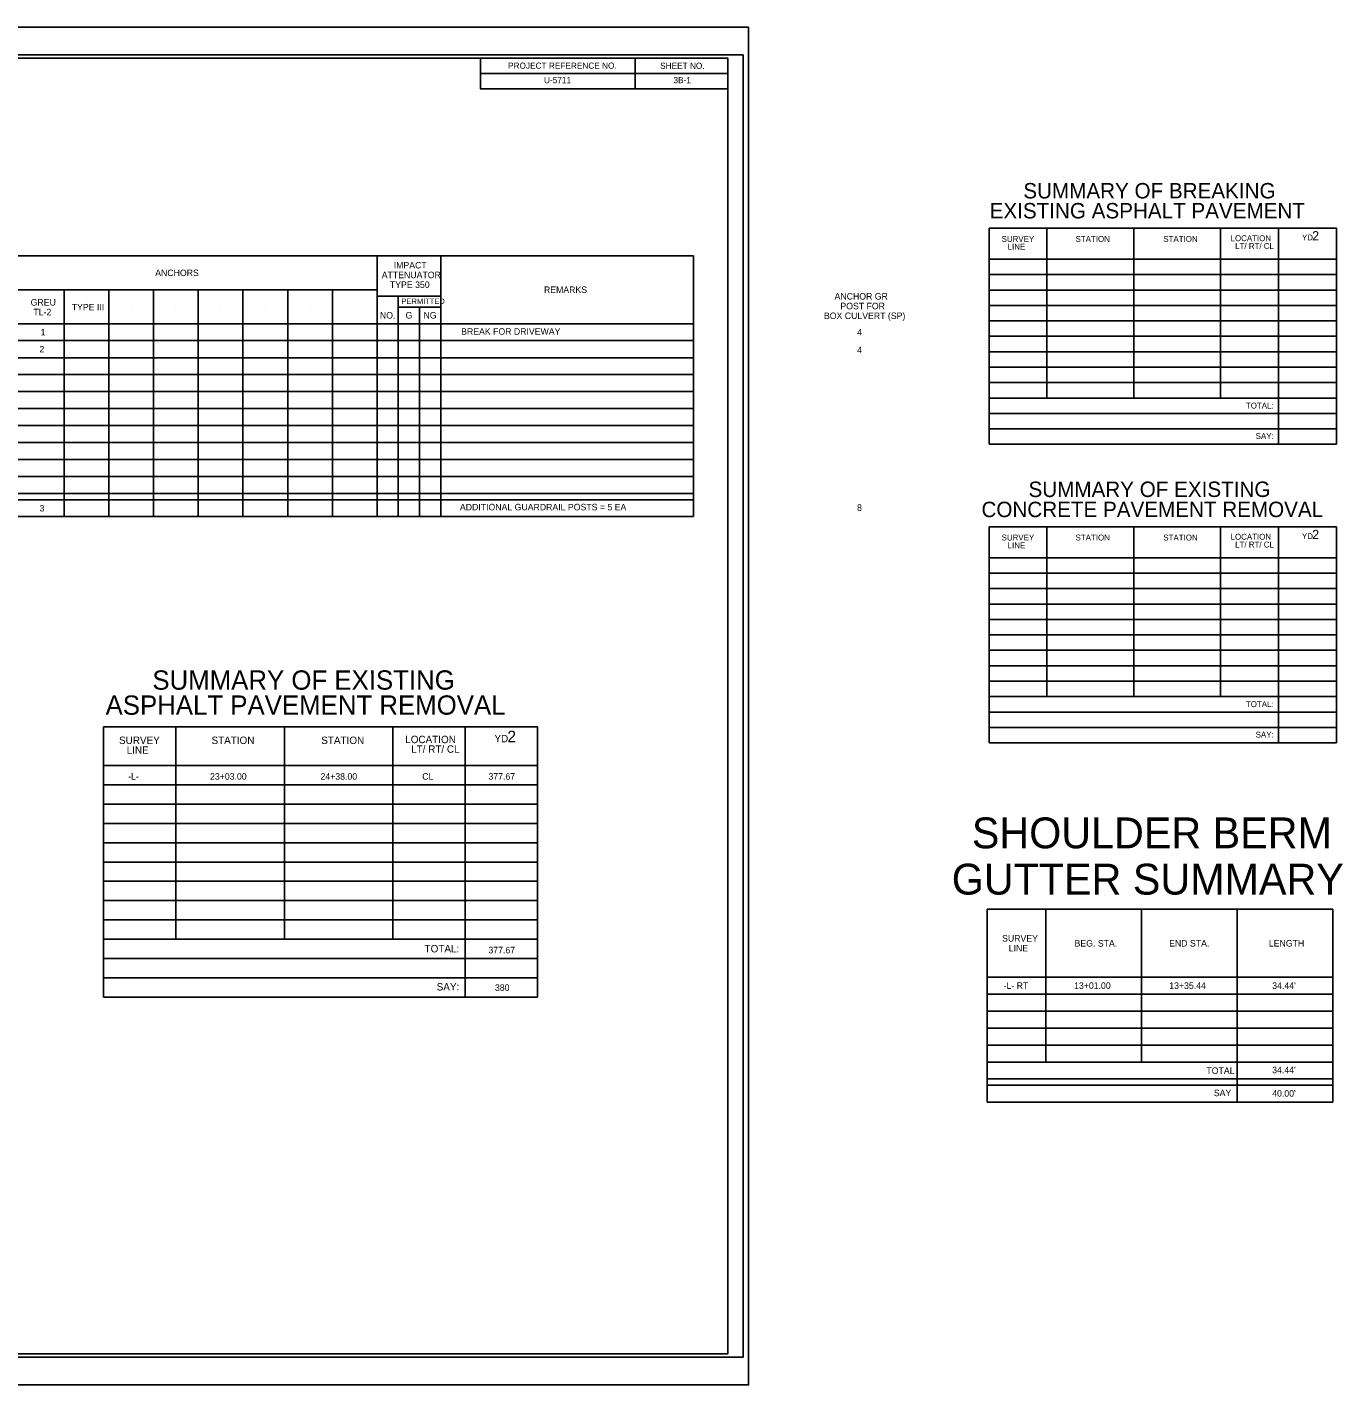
# Model space of a CAD drawing. Extents: x 1852861 to 1855026, y 258638 to 259738.
# Drawn here: x 1853961 to 1855026, y 258638 to 259738 of the extents above; entities that cross this region are included whole.
import ezdxf

# ---------------------------------------------------------------- set-up
doc = ezdxf.new("R2010")
doc.units = 0
for name, color, linetype in [('Old_Level_44', 7, 'Continuous'), ('Sheet Cutting Line CELL', 7, 'Continuous'), ('Sheet Plot Border Inside CELL', 7, 'Continuous'), ('Sheet Plot Border Outside CELL', 7, 'Continuous'), ('Sheet Summary Combination CELL', 7, 'Continuous'), ('Sheet Summary Combination Grid CELL', 7, 'Continuous'), ('Sheet Summary Guardrail CELL', 7, 'Continuous')]:
    doc.layers.add(name, color=color, linetype=linetype)

msp = doc.modelspace()

# ---------------------------------------------------------------- linework, layer by layer
at = {"layer": 'Sheet Cutting Line CELL'}
for p, q in [((1854545.1, 259738.5), (1852861.1, 259738.5)), ((1852861.1, 258638.5), (1854545.1, 258638.5))]:
    msp.add_line(p, q, dxfattribs=at)
at = {"layer": 'Sheet Plot Border Inside CELL'}
msp.add_lwpolyline([(1854540.6, 259716), (1852874.1, 259716), (1852874.1, 258660.9), (1854540.6, 258660.9)], close=True, dxfattribs=at)
at = {"layer": 'Sheet Plot Border Outside CELL'}
msp.add_lwpolyline([(1854545.1, 259738.5), (1852861.1, 259738.5), (1852861.1, 258638.5), (1854545.1, 258638.5)], close=True, dxfattribs=at)
at = {"layer": 'Sheet Summary Combination CELL'}
for p, q in [((1854453.1, 259713.4), (1854453.1, 259688.4)), ((1854328, 259700.9), (1854528.1, 259700.9)), ((1854328, 259688.4), (1854528.1, 259688.4)), ((1854881.1, 259575.5), (1854881.1, 259575.5)), ((1854887.3, 259575.4), (1854887.3, 259575.4)), ((1854896.4, 259575.6), (1854896.4, 259575.6)), ((1854902, 259575.5), (1854902, 259575.5)), ((1854881.1, 259333.6), (1854881.1, 259333.6)), ((1854887.3, 259333.5), (1854887.3, 259333.5)), ((1854896.4, 259333.7), (1854896.4, 259333.7)), ((1854902, 259333.6), (1854902, 259333.6)), ((1854199, 259171.4), (1854199, 259171.4)), ((1854206.8, 259171.3), (1854206.8, 259171.3)), ((1854218.1, 259171.5), (1854218.1, 259171.5)), ((1854225.1, 259171.4), (1854225.1, 259171.4))]:
    msp.add_line(p, q, dxfattribs=at)
for points in [[(1854528.1, 259713.5), (1853028.1, 259713.5), (1853028.1, 258663.5), (1854528.1, 258663.5)], [(1854328, 259713.5), (1854528.1, 259713.5), (1854528.1, 259688.4), (1854328, 259688.4)]]:
    msp.add_lwpolyline(points, close=True, dxfattribs=at)
at = {"layer": 'Sheet Summary Combination Grid CELL'}
for p, q in [((1854739.8, 259575.5), (1855021.2, 259575.5)), ((1854739.8, 259575.5), (1854739.8, 259400.5)), ((1854786.7, 259575.5), (1854786.7, 259438)), ((1854857.1, 259575.5), (1854857.1, 259438)), ((1854927.4, 259575.5), (1854927.4, 259438)), ((1854974.3, 259575.5), (1854974.3, 259400.5)), ((1855021.2, 259575.5), (1855021.2, 259400.5)), ((1854739.8, 259550.5), (1855021.2, 259550.5)), ((1854739.8, 259538), (1855021.2, 259538)), ((1854739.8, 259525.5), (1855021.2, 259525.5)), ((1854739.8, 259513), (1855021.2, 259513)), ((1854739.8, 259500.5), (1855021.2, 259500.5)), ((1854739.8, 259488), (1855021.2, 259488)), ((1854739.8, 259475.5), (1855021.2, 259475.5)), ((1854739.8, 259463), (1855021.2, 259463)), ((1854739.8, 259450.5), (1855021.2, 259450.5)), ((1854739.8, 259438), (1855021.2, 259438)), ((1854739.8, 259425.5), (1855021.2, 259425.5)), ((1854739.8, 259413), (1855021.2, 259413)), ((1854739.8, 259400.5), (1855021.2, 259400.5)), ((1854739.8, 259333.6), (1855021.2, 259333.6)), ((1854739.8, 259333.6), (1854739.8, 259158.6)), ((1854786.7, 259333.6), (1854786.7, 259196.1)), ((1854857.1, 259333.6), (1854857.1, 259196.1)), ((1854927.4, 259333.6), (1854927.4, 259196.1)), ((1854974.3, 259333.6), (1854974.3, 259158.6)), ((1855021.2, 259333.6), (1855021.2, 259158.6)), ((1854739.8, 259308.6), (1855021.2, 259308.6)), ((1854739.8, 259296.1), (1855021.2, 259296.1)), ((1854739.8, 259283.6), (1855021.2, 259283.6)), ((1854739.8, 259271.1), (1855021.2, 259271.1)), ((1854739.8, 259258.6), (1855021.2, 259258.6)), ((1854739.8, 259246.1), (1855021.2, 259246.1)), ((1854739.8, 259233.6), (1855021.2, 259233.6)), ((1854739.8, 259221.1), (1855021.2, 259221.1)), ((1854739.8, 259208.6), (1855021.2, 259208.6)), ((1854739.8, 259196.1), (1855021.2, 259196.1)), ((1854739.8, 259183.6), (1855021.2, 259183.6)), ((1854022.4, 259171.5), (1854374.1, 259171.5)), ((1854022.4, 259171.5), (1854022.4, 258952.7)), ((1854081.1, 259171.5), (1854081.1, 258999.6)), ((1854169, 259171.5), (1854169, 258999.6)), ((1854256.9, 259171.5), (1854256.9, 258999.6)), ((1854315.5, 259171.5), (1854315.5, 258952.7)), ((1854374.1, 259171.5), (1854374.1, 258952.7)), ((1854739.8, 259171.1), (1855021.2, 259171.1)), ((1854739.8, 259158.6), (1855021.2, 259158.6)), ((1854022.4, 259140.2), (1854374.1, 259140.2)), ((1854022.4, 259124.6), (1854374.1, 259124.6)), ((1854022.4, 259109), (1854374.1, 259109)), ((1854022.4, 259093.3), (1854374.1, 259093.3)), ((1854022.4, 259077.7), (1854374.1, 259077.7)), ((1854022.4, 259062.1), (1854374.1, 259062.1)), ((1854022.4, 259046.5), (1854374.1, 259046.5)), ((1854022.4, 259030.8), (1854374.1, 259030.8)), ((1854022.4, 259015.2), (1854374.1, 259015.2)), ((1854022.4, 258999.6), (1854374.1, 258999.6)), ((1854022.4, 258984), (1854374.1, 258984)), ((1854022.4, 258968.3), (1854374.1, 258968.3)), ((1854022.4, 258952.7), (1854374.1, 258952.7))]:
    msp.add_line(p, q, dxfattribs=at)
at = {"layer": 'Sheet Summary Guardrail CELL'}
for p, q in [((1853051.9, 259553.2), (1854500.3, 259553.2)), ((1854244.1, 259553.2), (1854244.1, 259341.9)), ((1854295.8, 259553.2), (1854295.8, 259341.9)), ((1854500.3, 259553.2), (1854500.3, 259341.9)), ((1854244.1, 259525.7), (1853736.1, 259525.7)), ((1853990.7, 259525.7), (1853990.7, 259341.9)), ((1854026.9, 259525.7), (1854026.9, 259341.9)), ((1854063.1, 259525.7), (1854063.1, 259341.9)), ((1854099.3, 259525.7), (1854099.3, 259341.9)), ((1854135.5, 259525.7), (1854135.5, 259341.9)), ((1854171.7, 259525.7), (1854171.7, 259341.9)), ((1854207.9, 259525.7), (1854207.9, 259341.9)), ((1854286, 259526), (1854286, 259526)), ((1854008.8, 259518.3), (1854008.8, 259518.3)), ((1854244.1, 259520.5), (1854295.8, 259520.5)), ((1854261.3, 259520.5), (1854261.3, 259341.9)), ((1853972.6, 259512), (1853972.6, 259512)), ((1854045, 259512), (1854045, 259512)), ((1854081.2, 259512), (1854081.2, 259512)), ((1854117.4, 259512), (1854117.4, 259512)), ((1854153.6, 259512), (1854153.6, 259512)), ((1854189.8, 259512), (1854189.8, 259512)), ((1854226, 259512), (1854226, 259512)), ((1854261.3, 259511.7), (1854295.8, 259511.7)), ((1854278.5, 259511.7), (1854278.5, 259341.9)), ((1853051.9, 259498.2), (1854500.3, 259498.2)), ((1853051.9, 259484.5), (1854500.3, 259484.5)), ((1853051.9, 259470.7), (1854500.3, 259470.7)), ((1853051.9, 259457), (1854500.3, 259457)), ((1853051.9, 259443.2), (1854500.3, 259443.2)), ((1853051.9, 259429.5), (1854500.3, 259429.5)), ((1853051.9, 259415.7), (1854500.3, 259415.7)), ((1853051.9, 259402), (1854500.3, 259402)), ((1853051.9, 259388.2), (1854500.3, 259388.2)), ((1853051.9, 259374.5), (1854500.3, 259374.5)), ((1853051.9, 259360.7), (1854500.3, 259360.7)), ((1853051.9, 259355.6), (1854500.3, 259355.6)), ((1853051.9, 259341.9), (1854500.3, 259341.9)), ((1854738.4, 259023.8), (1855018.4, 259023.8)), ((1854738.4, 259023.8), (1854738.4, 258867.4)), ((1854785.7, 259023.8), (1854785.7, 258900)), ((1854863.3, 259023.8), (1854863.3, 258900)), ((1854940.8, 259023.8), (1854940.8, 258867.4)), ((1855018.4, 259023.8), (1855018.4, 258867.4)), ((1854738.4, 258968.8), (1855018.4, 258968.8)), ((1854738.4, 258955), (1855018.4, 258955)), ((1854738.4, 258941.3), (1855018.4, 258941.3)), ((1854738.4, 258927.5), (1855018.4, 258927.5)), ((1854738.4, 258913.8), (1855018.4, 258913.8)), ((1854738.4, 258900), (1855018.4, 258900)), ((1854738.4, 258886.3), (1855018.4, 258886.3)), ((1854738.4, 258881.2), (1855018.4, 258881.2)), ((1854738.4, 258867.4), (1855018.4, 258867.4))]:
    msp.add_line(p, q, dxfattribs=at)

# ---------------------------------------------------------------- texts
at = {"layer": 'Old_Level_44'}
for s, p in [('U-5711', (1854379.3, 259693.1)), ('3B-1', (1854484.2, 259693.1))]:
    msp.add_text(s, height=5, dxfattribs=at).set_placement(p)
at = {"layer": 'Sheet Summary Combination CELL'}
for s, height, p in [('PROJECT REFERENCE NO.', 5, (1854350.2, 259704.8)), ('SHEET NO.', 5, (1854473.4, 259704.7)), ('SURVEY', 4.8, (1854750, 259564.5)), ('STATION', 4.8, (1854809.9, 259564.5)), ('STATION', 4.8, (1854881, 259564.5)), ('LOCATION', 4.8, (1854935.5, 259565.1)), ('LINE', 4.8, (1854754.9, 259558.2)), ('LT/ RT/ CL', 4.8, (1854939.2, 259558.8)), ('TOTAL:', 4.8, (1854947.9, 259429.5)), ('SAY:', 4.8, (1854955.8, 259404.8)), ('SURVEY', 4.8, (1854750, 259322.6)), ('STATION', 4.8, (1854809.9, 259322.6)), ('STATION', 4.8, (1854881, 259322.6)), ('LOCATION', 4.8, (1854935.5, 259323.2)), ('LINE', 4.8, (1854754.9, 259316.3)), ('LT/ RT/ CL', 4.8, (1854939.2, 259316.9)), ('TOTAL:', 4.8, (1854947.9, 259187.6)), ('SURVEY', 6, (1854035.1, 259157.7)), ('STATION', 6, (1854110, 259157.7)), ('STATION', 6, (1854198.9, 259157.7)), ('LOCATION', 6, (1854266.9, 259158.4)), ('SAY:', 4.8, (1854955.8, 259162.9)), ('LINE', 6, (1854041.3, 259149.8)), ('LT/ RT/ CL', 6, (1854271.7, 259150.6)), ('TOTAL:', 6, (1854282.6, 258988.9)), ('SAY:', 6, (1854292.4, 258958))]:
    msp.add_text(s, height=height, dxfattribs=at).set_placement(p)
for s, height, p in [('SUMMARY OF BREAKING', 12.5, (1854767.6, 259599.7)), ('EXISTING ASPHALT PAVEMENT', 12.5, (1854740.3, 259583.5)), ('SUMMARY OF EXISTING', 12.5, (1854771.8, 259357.8)), ('CONCRETE PAVEMENT REMOVAL', 12.5, (1854733.7, 259341.5)), ('SUMMARY OF EXISTING', 15.625, (1854062.1, 259201.7)), ('ASPHALT PAVEMENT REMOVAL', 15.625, (1854024.2, 259181.4))]:
    msp.add_text(s, height=height, rotation=0.0119, dxfattribs=at).set_placement(p)
at = {"layer": 'Sheet Summary Combination Grid CELL'}
for s, height, p in [('YD', 4.8, (1854993.3, 259565.7)), ('2', 7.5, (1855001.6, 259565.7)), ('YD', 4.8, (1854993.3, 259323.7)), ('2', 7.5, (1855001.6, 259323.7)), ('YD', 6, (1854339.2, 259159.1)), ('2', 9.38, (1854349.7, 259159.1))]:
    msp.add_text(s, height=height, dxfattribs=at).set_placement(p)
at = {"layer": 'Sheet Summary Guardrail CELL'}
for s, height, p in [('IMPACT', 5.28, (1854257.6, 259543)), ('ANCHORS', 5.28, (1854064.4, 259536.8)), ('ATTENUATOR', 5.28, (1854247.9, 259535.1)), ('TYPE 350', 5.28, (1854254.5, 259527.2)), ('REMARKS', 5.28, (1854379.3, 259523.1)), ('ANCHOR GR', 5.28, (1854614.7, 259517.8)), ('GREU', 5.28, (1853963.5, 259512.9)), ('TYPE III', 5.28, (1853996.8, 259509)), ('PERMITTED', 4.4, (1854263.9, 259514.2)), ('POST FOR', 5.28, (1854619.4, 259509.9)), ('TL-2', 5.28, (1853965.7, 259505)), ('NO.', 5.28, (1854246.4, 259502.4)), ('G', 5.28, (1854267.2, 259502.4)), ('NG', 5.28, (1854281.7, 259502.4)), ('BOX CULVERT (SP)', 5.28, (1854606.1, 259502)), ('1', 5.28, (1853971.5, 259488.7)), ('BREAK FOR DRIVEWAY', 5.28, (1854312.2, 259489.3)), ('4', 5.28, (1854633, 259488.7)), ('2', 5.28, (1853970.6, 259474.9)), ('4', 5.28, (1854633, 259474.4)), ('3', 5.28, (1853970.7, 259346.1)), ('ADDITIONAL GUARDRAIL POSTS = 5 EA', 5.28, (1854311.2, 259347)), ('8', 5.28, (1854632.9, 259346.6)), ('-L-', 5.28, (1854042.5, 259128.8)), ('23+03.00', 5.28, (1854108.8, 259128.8)), ('24+38.00', 5.28, (1854198.3, 259128.8)), ('CL', 5.28, (1854280.7, 259128.8)), ('377.67', 5.28, (1854334.3, 259128.8)), ('SHOULDER BERM', 25, (1854725.9, 259073.2)), ('GUTTER SUMMARY', 25, (1854709.6, 259035.7)), ('SURVEY', 5.28, (1854750.4, 258997.6)), ('BEG. STA.', 5.28, (1854809.1, 258993.6)), ('END STA.', 5.28, (1854885.7, 258993.6)), ('LENGTH', 5.28, (1854966.5, 258993.6)), ('377.67', 5.28, (1854334.3, 258988.1)), ('LINE', 5.28, (1854755.8, 258989.6)), ('380', 5.28, (1854339.6, 258957.7)), ('-L- RT', 5.28, (1854751.6, 258959.3)), ('13+01.00', 5.28, (1854808.7, 258959.3)), ('13+35.44', 5.28, (1854885.8, 258959.3)), ("34.44'", 5.28, (1854969.2, 258959.3)), ("34.44'", 5.28, (1854969.2, 258891)), ('TOTAL', 5.28, (1854915.9, 258890.4)), ('SAY', 5.28, (1854921.9, 258872.4)), ("40.00'", 5.28, (1854969.2, 258872))]:
    msp.add_text(s, height=height, dxfattribs=at).set_placement(p)

doc.saveas('drawing.dxf')
